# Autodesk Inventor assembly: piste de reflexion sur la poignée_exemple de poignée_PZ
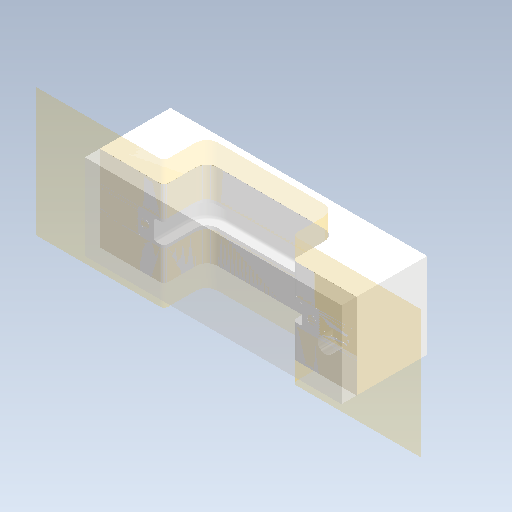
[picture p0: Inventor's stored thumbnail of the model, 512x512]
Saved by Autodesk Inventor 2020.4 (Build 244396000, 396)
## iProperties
Created: 2021-10
Part Number: piste de reflexion sur la poignée_exemple de poignée_PZ
Document SubType Name: Assembly
Designer: mel
Author: mel
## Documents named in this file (7)
- D:\travail\année 2020-2021\itec\prépa injection plastique eduscol\dossier de travail\Ensemble des pièces de l'activité\Conception de moule2\piste de reflexion sur la poignée_exemple de poignée_PZ.iam
- D:\travail\année 2020-2021\itec\prépa injection plastique eduscol\dossier de travail\Ensemble des pièces de l'activité\Conception de moule2\piste de reflexion sur la poignée_exemple de poignée_MP.ipt
- D:\travail\année 2020-2021\itec\prépa injection plastique eduscol\dossier de travail\Ensemble des pièces de l'activité\Conception de moule2\piste de reflexion sur la poignée_exemple de poignée_WP.ipt
- D:\travail\année 2020-2021\itec\prépa injection plastique eduscol\dossier de travail\Ensemble des pièces de l'activité\Conception de moule2\piste de reflexion sur la poignée_exemple de poignée_CR_Base.ipt
- D:\travail\année 2020-2021\itec\prépa injection plastique eduscol\dossier de travail\Ensemble des pièces de l'activité\Conception de moule2\piste de reflexion sur la poignée_exemple de poignée_CR_1.ipt
- D:\travail\année 2020-2021\itec\prépa injection plastique eduscol\dossier de travail\Ensemble des pièces de l'activité\Conception de moule2\piste de reflexion sur la poignée_exemple de poignée_CV_Base.ipt
- D:\travail\année 2020-2021\itec\prépa injection plastique eduscol\dossier de travail\Ensemble des pièces de l'activité\Conception de moule2\piste de reflexion sur la poignée_exemple de poignée_CV_1.ipt
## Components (6 placed, 6 different names)
1. piste de reflexion sur la poignée_exemple de poignée_MP:1 — Affleurement:1, Affleurement:2, Affleurement:3, Affleurement:4, Affleurement:5, Affleurement:6
2. piste de reflexion sur la poignée_exemple de poignée_WP:1 — Affleurement:4, Affleurement:5, Affleurement:6
3. piste de reflexion sur la poignée_exemple de poignée_CR_Base:1 — Affleurement:7, Affleurement:8, Affleurement:9, Affleurement:13, Affleurement:14, Affleurement:15
4. piste de reflexion sur la poignée_exemple de poignée_CR_1:1 — Affleurement:13, Affleurement:14, Affleurement:15
5. piste de reflexion sur la poignée_exemple de poignée_CV_Base:1 — Affleurement:10, Affleurement:11, Affleurement:12, Affleurement:16, Affleurement:17, Affleurement:18
6. piste de reflexion sur la poignée_exemple de poignée_CV_1:1 — Affleurement:16, Affleurement:17, Affleurement:18
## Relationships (18: Flush 18)
- Affleurement:1 [Flush]: piste de reflexion sur la poignée_exemple de poignée_MP:1
- Affleurement:2 [Flush]: piste de reflexion sur la poignée_exemple de poignée_MP:1
- Affleurement:3 [Flush]: piste de reflexion sur la poignée_exemple de poignée_MP:1
- Affleurement:4 [Flush]: piste de reflexion sur la poignée_exemple de poignée_MP:1 ↔ piste de reflexion sur la poignée_exemple de poignée_WP:1
- Affleurement:5 [Flush]: piste de reflexion sur la poignée_exemple de poignée_MP:1 ↔ piste de reflexion sur la poignée_exemple de poignée_WP:1
- Affleurement:6 [Flush]: piste de reflexion sur la poignée_exemple de poignée_MP:1 ↔ piste de reflexion sur la poignée_exemple de poignée_WP:1
- Affleurement:7 [Flush]: piste de reflexion sur la poignée_exemple de poignée_CR_Base:1
- Affleurement:8 [Flush]: piste de reflexion sur la poignée_exemple de poignée_CR_Base:1
- Affleurement:9 [Flush]: piste de reflexion sur la poignée_exemple de poignée_CR_Base:1
- Affleurement:10 [Flush]: piste de reflexion sur la poignée_exemple de poignée_CV_Base:1
- Affleurement:11 [Flush]: piste de reflexion sur la poignée_exemple de poignée_CV_Base:1
- Affleurement:12 [Flush]: piste de reflexion sur la poignée_exemple de poignée_CV_Base:1
- Affleurement:13 [Flush]: piste de reflexion sur la poignée_exemple de poignée_CR_Base:1 ↔ piste de reflexion sur la poignée_exemple de poignée_CR_1:1
- Affleurement:14 [Flush]: piste de reflexion sur la poignée_exemple de poignée_CR_Base:1 ↔ piste de reflexion sur la poignée_exemple de poignée_CR_1:1
- Affleurement:15 [Flush]: piste de reflexion sur la poignée_exemple de poignée_CR_Base:1 ↔ piste de reflexion sur la poignée_exemple de poignée_CR_1:1
- Affleurement:16 [Flush]: piste de reflexion sur la poignée_exemple de poignée_CV_Base:1 ↔ piste de reflexion sur la poignée_exemple de poignée_CV_1:1
- Affleurement:17 [Flush]: piste de reflexion sur la poignée_exemple de poignée_CV_Base:1 ↔ piste de reflexion sur la poignée_exemple de poignée_CV_1:1
- Affleurement:18 [Flush]: piste de reflexion sur la poignée_exemple de poignée_CV_Base:1 ↔ piste de reflexion sur la poignée_exemple de poignée_CV_1:1
